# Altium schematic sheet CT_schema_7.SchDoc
size 365 x 245 mm
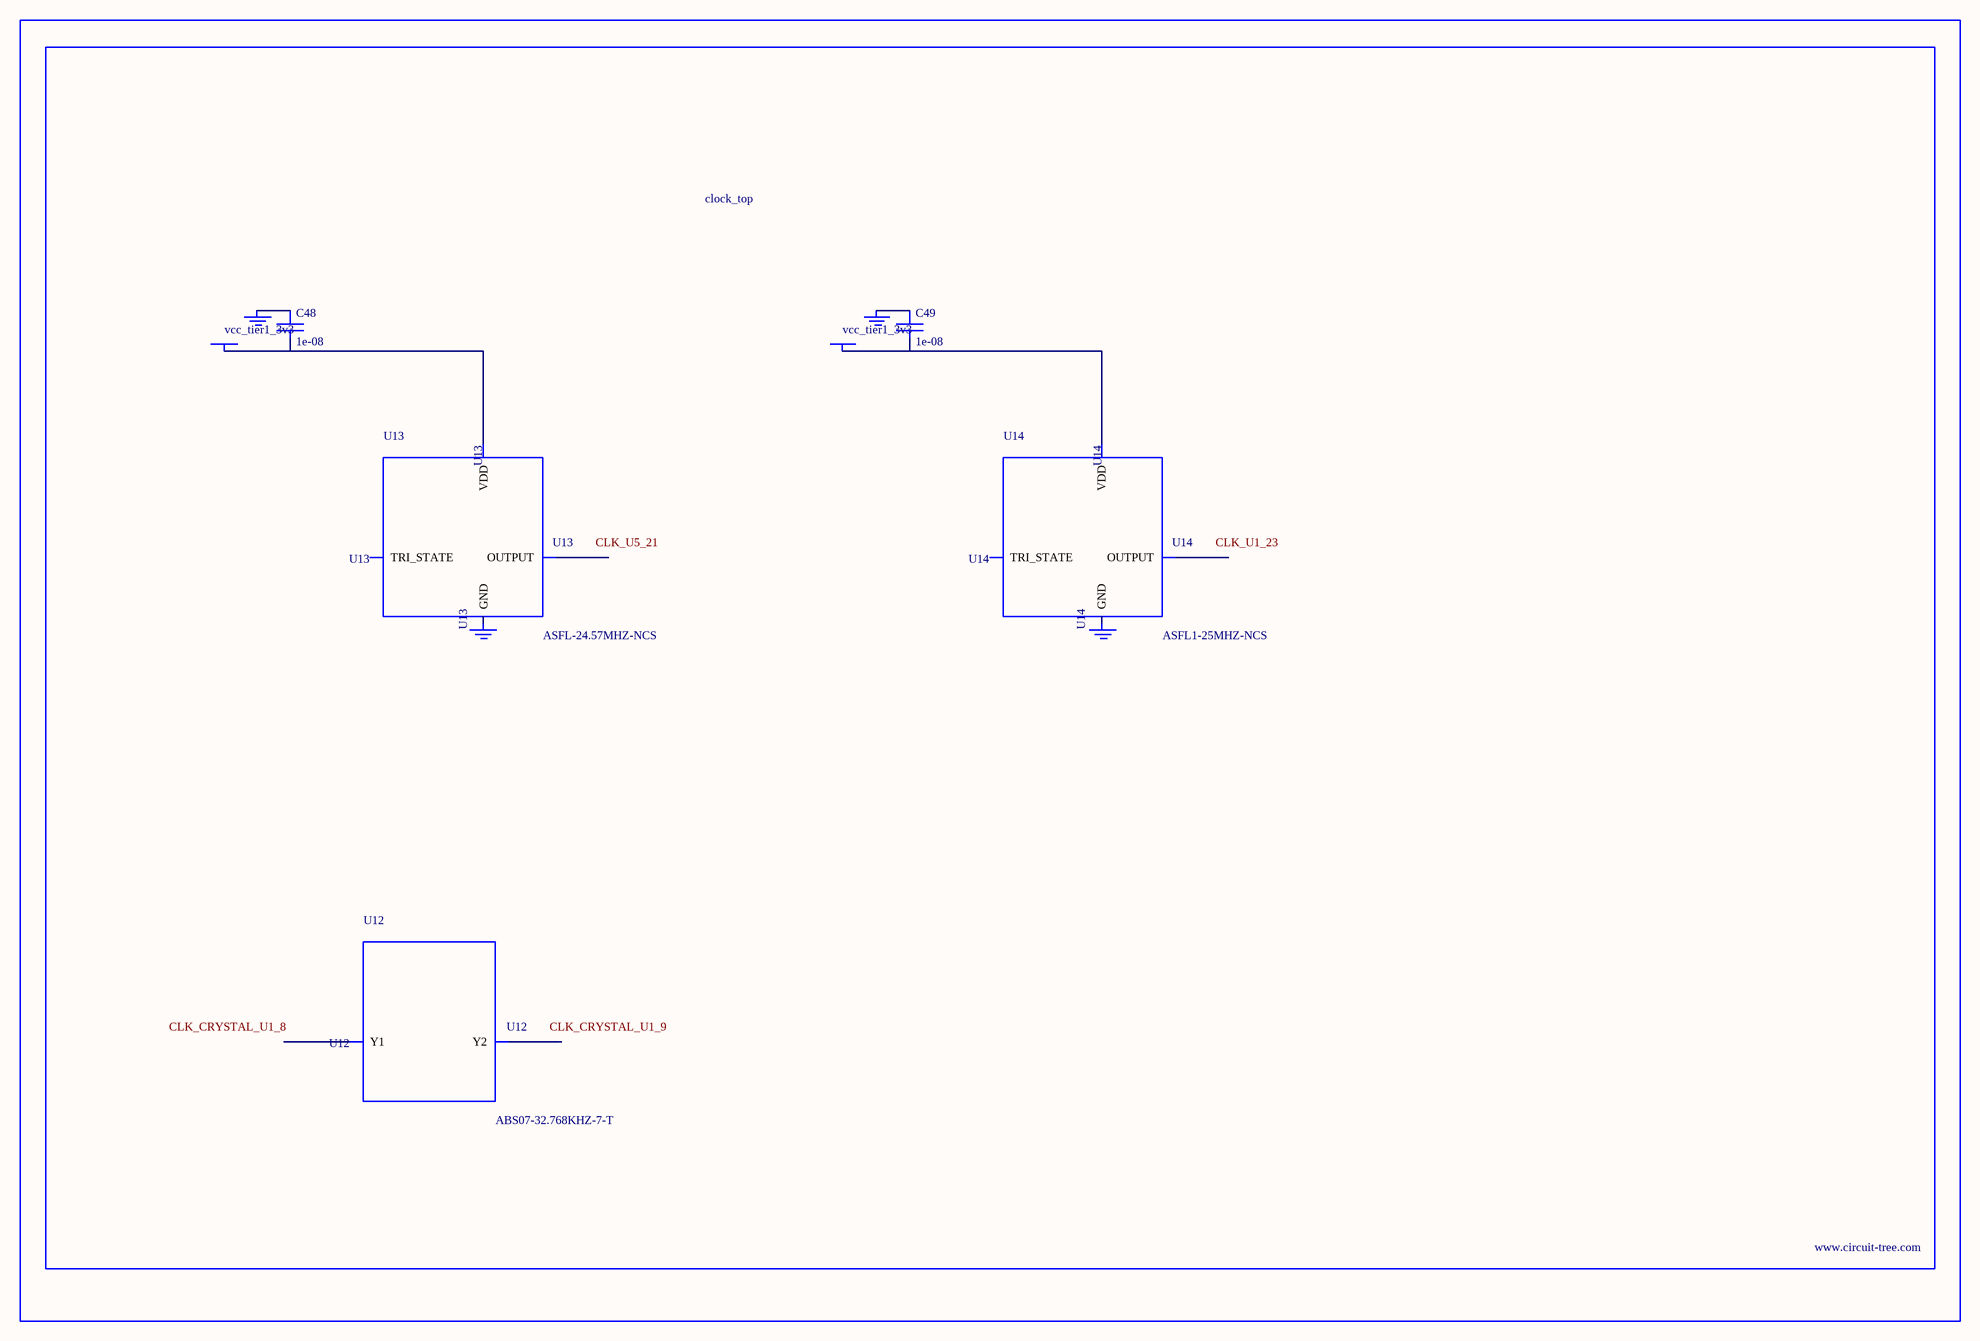
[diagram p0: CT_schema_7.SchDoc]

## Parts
BORDER6  (no value)
C48  1e-08  [C0402]
C49  1e-08  [C0402]
GND_INSTANCE_6_0  (no value)
GND_INSTANCE_6_1  (no value)
GND_INSTANCE_6_2  (no value)
GND_INSTANCE_6_3  (no value)
POWER_INSTANCE_6_0  vcc_tier1_3v3
POWER_INSTANCE_6_1  vcc_tier1_3v3
U12  ABS07-32.768KHZ-7-T  [ABS07-32.768KHZ-7-T]
U13  ASFL-24.57MHZ-NCS  [ASFL1]
U14  ASFL1-25MHZ-NCS  [ASFL1]

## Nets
NetC48_1: C48.1 GND_INSTANCE_6_0.0(GND)
NetC48_2: C48.2 POWER_INSTANCE_6_0.0(PWR) U13.4(VDD)
NetC49_1: C49.1 GND_INSTANCE_6_2.0(GND)
NetC49_2: C49.2 POWER_INSTANCE_6_1.0(PWR) U14.4(VDD)

Not connected (* = marked no-connect by the designer): GND_INSTANCE_6_1 0(GND); GND_INSTANCE_6_3 0(GND); U12 1(Y1) 2(Y2); U13 1(TRI_STATE) 2(GND) 3(OUTPUT); U14 1(TRI_STATE) 2(GND) 3(OUTPUT)

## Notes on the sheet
- Labels drawn without touching a wire or pin: CLK_CRYSTAL_U1_8, CLK_CRYSTAL_U1_9, CLK_U1_23, CLK_U5_21

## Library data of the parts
BORDER6 = BORDER_PAGE6
C48 C49 = C0402C103K3RAC
GND_INSTANCE_6_0-GND_INSTANCE_6_3 = GND
POWER_INSTANCE_6_0 POWER_INSTANCE_6_1 = PWR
